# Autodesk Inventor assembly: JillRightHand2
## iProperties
Company: cbliss@cbliss.com
Author: Charles Bliss
Shininess: 0.0
PropertySet Name: _Private Model Information
Created: 2000-01
Part Number: JillRightHand2
Project: Inventor Sample
Document SubType Name: Assembly
Designer: Charles Bliss
Control State: 0
Checked Out: False
Master: False
Density: 0.0
Volume: 0.0
Area: 0.0
PropertySet Name: Model Information
